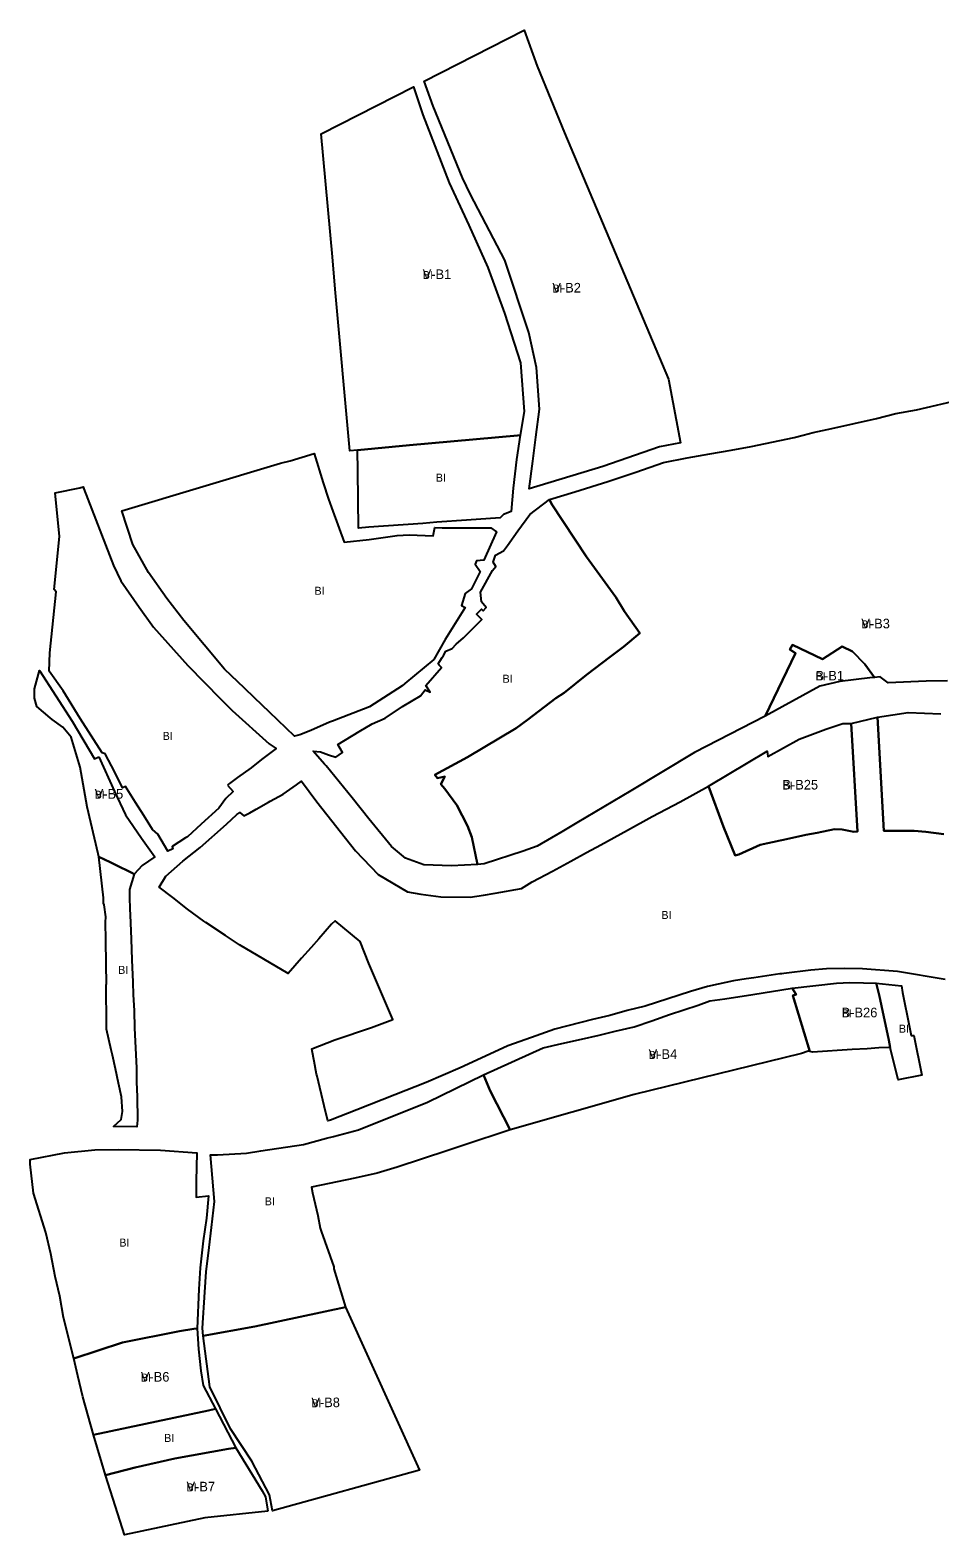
# Model space of a CAD drawing. Extents: x -532081 to -530154, y -1179372 to -1177675.
# Drawn here: x -532081 to -531512, y -1178734 to -1177794 of the extents above; entities that cross this region are included whole.
import ezdxf

# ---------------------------------------------------------------- set-up
doc = ezdxf.new("R2010")
doc.units = 0
for name, color, linetype in [('90040013', 7, 'Continuous'), ('90040023', 7, 'Continuous'), ('ID_navrh', 7, 'Continuous')]:
    doc.layers.add(name, color=color, linetype=linetype)

msp = doc.modelspace()

# ---------------------------------------------------------------- linework, layer by layer
at = {"layer": '90040013'}
for points in [[(-531869.34, -1178104.69), (-531875.73, -1178105.32), (-531876.21, -1178069.69), (-531876.39, -1178056.56), (-531843.89, -1178053.44), (-531776.3, -1178047.25), (-531774.57, -1178047.09), (-531777.03, -1178062.36), (-531779.14, -1178080.32), (-531780.38, -1178094.84), (-531785, -1178096.75), (-531787.18, -1178098.75), (-531808.2, -1178100.27), (-531826.84, -1178101.48), (-531835.46, -1178102.28)], [(-531891.83, -1178094.67), (-531884.75, -1178114.05), (-531869.14, -1178112.33), (-531851.53, -1178109.85), (-531844.08, -1178109.36), (-531828.99, -1178110.03), (-531827.93, -1178104.93), (-531823.39, -1178104.95), (-531808.92, -1178104.95), (-531792.99, -1178104.95), (-531789.36, -1178107.5), (-531797.35, -1178125.35), (-531801.89, -1178125.72), (-531802.8, -1178127.72), (-531799.71, -1178132.28), (-531805.16, -1178143.21), (-531808.97, -1178146.12), (-531811.33, -1178153.49), (-531809.01, -1178154.87), (-531821.49, -1178174.83), (-531828.69, -1178187.35), (-531846.79, -1178202.32), (-531848.46, -1178203.7), (-531868.8, -1178216.93), (-531892, -1178225.95), (-531893.87, -1178226.53), (-531905.46, -1178231.71), (-531912.28, -1178234.48), (-531915.73, -1178235.21), (-531931.35, -1178220.27), (-531940.66, -1178211.34), (-531947.04, -1178205.21), (-531959.4, -1178193.44), (-531984.96, -1178162.97), (-531995.52, -1178149.27), (-532006.96, -1178132.89), (-532016.83, -1178115.38), (-532023.59, -1178094.39), (-531924.56, -1178064.67), (-531918.32, -1178063.14), (-531903.47, -1178058.5), (-531897.72, -1178076.91), (-531894.55, -1178087.08)], [(-531957.63, -1178265.86), (-531953.96, -1178269.83), (-531958.6, -1178274.13), (-531962.95, -1178280.23), (-531974.02, -1178290.23), (-531982.67, -1178298.09), (-531983.81, -1178298.74), (-531992.09, -1178304.24), (-531991.69, -1178305.71), (-531994.9, -1178307.05), (-532001.07, -1178296.47), (-532004.5, -1178293.46), (-532009.87, -1178284.73), (-532015.13, -1178276.66), (-532021.24, -1178266.65), (-532023.21, -1178267.49), (-532028.1, -1178257.78), (-532034.09, -1178246.23), (-532035.93, -1178245.59), (-532049.67, -1178224.22), (-532060.29, -1178206.94), (-532069.01, -1178194.64), (-532068.69, -1178183.15), (-532064.73, -1178145.04), (-532066.02, -1178143.52), (-532062.58, -1178110.48), (-532065.33, -1178083.08), (-532049.98, -1178080.01), (-532047.73, -1178079.39), (-532047.4, -1178080.59), (-532028.78, -1178128.58), (-532024.19, -1178138.06), (-532012.87, -1178154.65), (-532003.91, -1178167.19), (-531982.44, -1178191.09), (-531961.68, -1178212.15), (-531954.6, -1178219.23), (-531931.63, -1178239.92), (-531927.24, -1178243.01), (-531936.39, -1178249.88), (-531942.73, -1178255.03), (-531951.41, -1178260.97), (-531956.26, -1178264.79), (-531956.93, -1178265.31)], [(-531714.94, -1178148.44), (-531709.43, -1178157.35), (-531699.82, -1178170.92), (-531710.05, -1178179.32), (-531718.44, -1178185.63), (-531733.12, -1178196.99), (-531747.18, -1178208.14), (-531752.37, -1178211.56), (-531770.1, -1178225.04), (-531777.2, -1178230.28), (-531807.62, -1178248.25), (-531827.96, -1178259.3), (-531826.25, -1178261.4), (-531821.69, -1178260.38), (-531824.23, -1178265.13), (-531821.77, -1178268.08), (-531814.18, -1178278.37), (-531807.61, -1178291.18), (-531804.87, -1178298.29), (-531801.44, -1178315.51), (-531817.69, -1178316.31), (-531834.9, -1178315.65), (-531846.42, -1178311.41), (-531855.06, -1178304.09), (-531869.28, -1178286.94), (-531879.65, -1178273.84), (-531895.97, -1178253.81), (-531896.87, -1178252.79), (-531904.04, -1178244.56), (-531899.49, -1178245.11), (-531894.41, -1178246.98), (-531889.85, -1178248.33), (-531885.68, -1178245.39), (-531888.72, -1178240.33), (-531875.23, -1178232.22), (-531867.25, -1178227.42), (-531859.06, -1178223.97), (-531848.13, -1178216.78), (-531837.01, -1178210), (-531834.12, -1178206.37), (-531830.91, -1178207.69), (-531833.63, -1178203.57), (-531823.9, -1178192.31), (-531825.21, -1178190.76), (-531825.87, -1178190.09), (-531824.89, -1178188.43), (-531823.49, -1178186.1), (-531822.67, -1178184.72), (-531821.08, -1178182.07), (-531817.23, -1178180.54), (-531814.7, -1178177.72), (-531810.08, -1178173.81), (-531800.1, -1178163.76), (-531798.6, -1178162.25), (-531801.88, -1178159), (-531798.82, -1178155.91), (-531797.83, -1178156.89), (-531795.83, -1178154.86), (-531798.8, -1178151.21), (-531799.42, -1178145.22), (-531792, -1178131.78), (-531789.8, -1178129.25), (-531791.49, -1178126.58), (-531790.08, -1178122.22), (-531785.18, -1178119.41), (-531782.65, -1178116.18), (-531776.13, -1178106.97), (-531768.71, -1178096.63), (-531756.44, -1178087.34), (-531755, -1178090.04), (-531733.11, -1178123.17)], [(-532013.79, -1178475.22), (-532014.33, -1178479.27), (-532028.88, -1178479.11), (-532023.99, -1178474.68), (-532023.15, -1178469.65), (-532023.87, -1178460.56), (-532025.66, -1178452.06), (-532027.68, -1178443.08), (-532029.51, -1178434.55), (-532030.37, -1178431.2), (-532033.16, -1178418.37), (-532033.27, -1178408.02), (-532033.47, -1178398.43), (-532033.47, -1178390.78), (-532033.25, -1178389.75), (-532033.47, -1178377.87), (-532033.47, -1178375.7), (-532033.7, -1178364.62), (-532033.7, -1178362.79), (-532033.82, -1178351.49), (-532033.57, -1178348.18), (-532034.76, -1178340.69), (-532035.1, -1178339.5), (-532035.1, -1178336.26), (-532037.98, -1178310.72), (-532030.86, -1178314.03), (-532027.54, -1178315.67), (-532017.48, -1178320.54), (-532015.89, -1178321.4), (-532018.86, -1178331.08), (-532018.86, -1178335.75), (-532018.61, -1178343.24), (-532018.49, -1178346.95), (-532017.74, -1178362.07), (-532017.37, -1178374.95), (-532016.81, -1178388.95), (-532016.63, -1178396.79), (-532015.88, -1178406.69), (-532015.7, -1178417.7), (-532015.14, -1178430.02), (-532014.44, -1178442.73), (-532014.44, -1178451.36), (-532014.05, -1178460.32)], [(-531531.32, -1178416.98), (-531530.29, -1178422.29), (-531528.71, -1178422.29), (-531523.7, -1178447.15), (-531538.47, -1178450.06), (-531543.48, -1178429.7), (-531544.27, -1178425.2), (-531548.91, -1178403.63), (-531550.26, -1178396.86), (-531552.21, -1178389.46), (-531536.27, -1178391.25), (-531535.62, -1178395.45)], [(-531940.58, -1178604.17), (-531972.85, -1178609.96), (-531973.25, -1178605.17), (-531971.85, -1178582.59), (-531970.86, -1178570), (-531969.07, -1178554.82), (-531967.59, -1178542.25), (-531965.63, -1178526.01), (-531968.12, -1178496.73), (-531963.85, -1178496.73), (-531945.7, -1178495.84), (-531936.8, -1178494.41), (-531910.1, -1178490.3), (-531895.69, -1178486.37), (-531891.41, -1178485.3), (-531875.76, -1178481.16), (-531832.63, -1178463.86), (-531797.68, -1178446.78), (-531793.48, -1178456.76), (-531780.88, -1178481.16), (-531809.85, -1178490.7), (-531819.98, -1178494.04), (-531851.65, -1178504.46), (-531864.04, -1178508.23), (-531878.07, -1178511.37), (-531905.12, -1178517.08), (-531904.53, -1178520.65), (-531901.14, -1178534.84), (-531899.7, -1178542.72), (-531898.95, -1178544.63), (-531891.18, -1178566.81), (-531891.18, -1178568), (-531883.81, -1178591.98)], [(-531977.26, -1178513.35), (-531977.26, -1178523.38), (-531969.43, -1178522.51), (-531970.74, -1178536.47), (-531972.7, -1178550.65), (-531974.65, -1178567.45), (-531975.52, -1178580.76), (-531976.57, -1178605.34), (-531978.58, -1178605.47), (-531987.54, -1178606.95), (-532023.25, -1178614.06), (-532053.53, -1178624.01), (-532060.1, -1178598.44), (-532062.47, -1178585.16), (-532065.23, -1178572.87), (-532068, -1178558.59), (-532071.1, -1178545.26), (-532078.93, -1178520.84), (-532080.97, -1178502.73), (-532080.97, -1178499.83), (-532059.55, -1178495.65), (-532040.48, -1178493.77), (-532026.01, -1178493.6), (-531999.45, -1178493.94), (-531976.8, -1178495.48)], [(-532015.3, -1178692.16), (-532033.93, -1178696.89), (-532041.26, -1178671.72), (-531969.39, -1178656.5), (-531965.15, -1178655.59), (-531952.37, -1178679.96), (-531956.87, -1178680.49), (-531990.45, -1178686.59)]]:
    msp.add_lwpolyline(points, close=True, dxfattribs=at)
msp.add_lwpolyline([(-531509.09, -1178387.21), (-531538.87, -1178382.3), (-531560.69, -1178380.6), (-531571.79, -1178380.41), (-531583.26, -1178380.6), (-531593.04, -1178381.35), (-531609.9, -1178383.53), (-531611.14, -1178383.8), (-531612.42, -1178383.8), (-531628.65, -1178386.19), (-531633.42, -1178386.91), (-531641.39, -1178388), (-531650.92, -1178390.16), (-531657.57, -1178391.6), (-531668.17, -1178394.67), (-531682.37, -1178399.25), (-531696.58, -1178403.83), (-531707.74, -1178406.63), (-531718.65, -1178409.69), (-531729.56, -1178412.23), (-531752.9, -1178418.34), (-531767.61, -1178423.43), (-531782.4, -1178428.62), (-531790.92, -1178432.6), (-531812.21, -1178442.57), (-531833.5, -1178451.7), (-531852.91, -1178459.31), (-531876.82, -1178468.63), (-531893.14, -1178475.26), (-531894.97, -1178475.68), (-531897.08, -1178466.23), (-531901.62, -1178447.73), (-531901.86, -1178446.33), (-531903.43, -1178438.26), (-531904.67, -1178431.8), (-531904.95, -1178430.53), (-531890.47, -1178424.89), (-531867.54, -1178417.27), (-531854.32, -1178412.33), (-531869.19, -1178377.34), (-531874.74, -1178363.59), (-531890.35, -1178350.54), (-531892.61, -1178352.62), (-531900.59, -1178361.85), (-531905.28, -1178367.24), (-531911.35, -1178373.86), (-531919.68, -1178383.6), (-531950.07, -1178365.6), (-531958.9, -1178359.83), (-531971.17, -1178351.55), (-531972.28, -1178350.74), (-531982.49, -1178343.28), (-531991.84, -1178336.1), (-532000.2, -1178329.58), (-531996.17, -1178322.74), (-531985.49, -1178313.42), (-531974.76, -1178304.88), (-531958.11, -1178290.13), (-531951.73, -1178284.22), (-531949.8, -1178282.87), (-531947.36, -1178285.05), (-531943.73, -1178283.03), (-531939.62, -1178280.75), (-531932.03, -1178276.53), (-531930.84, -1178275.92), (-531922.86, -1178271.53), (-531914.53, -1178265.55), (-531911.34, -1178263.25), (-531901.73, -1178276.35), (-531877.53, -1178306.79), (-531863.37, -1178321.76), (-531845.04, -1178332.53), (-531836.71, -1178334.01), (-531824.31, -1178335.68), (-531805.98, -1178335.87), (-531797.65, -1178334.57), (-531790.25, -1178333.27), (-531773.77, -1178330.49), (-531767.11, -1178326.21), (-531754.53, -1178319.68), (-531743.05, -1178313.37), (-531733.24, -1178307.98), (-531724.17, -1178303.16), (-531707.69, -1178293.87), (-531692.14, -1178285.33), (-531674.73, -1178276.23), (-531656.96, -1178266.46), (-531647.51, -1178291.8), (-531640.37, -1178309.78), (-531638.81, -1178309.43), (-531637.97, -1178309.1), (-531624.62, -1178303.19), (-531612.27, -1178300.39), (-531611.07, -1178300.19), (-531602.5, -1178298.39), (-531596.13, -1178296.79), (-531588.96, -1178295.6), (-531578.2, -1178293.4), (-531573.42, -1178293.6), (-531566.05, -1178295), (-531563.86, -1178294.8), (-531567.74, -1178227.33), (-531551.32, -1178223.26), (-531547.32, -1178294.4), (-531533.38, -1178294.4), (-531528.4, -1178294.43), (-531521.2, -1178294.91), (-531509.87, -1178296.36)], dxfattribs=at)
at = {"layer": '90040023'}
for points in [[(-531681.94, -1178012.18), (-531674.51, -1178052.02), (-531687.56, -1178054.45), (-531722.99, -1178066.65), (-531768.97, -1178080.72), (-531766.81, -1178063.34), (-531764.84, -1178048.37), (-531762.55, -1178030.99), (-531764.36, -1178004.77), (-531769.2, -1177983.08), (-531784.19, -1177937.7), (-531805.73, -1177896.68), (-531810.63, -1177886.29), (-531829.04, -1177841.54), (-531834.6, -1177825.98), (-531772.14, -1177794.03), (-531764.08, -1177816.59), (-531746.96, -1177858.19)], [(-531806.82, -1177915.91), (-531794.88, -1177942.31), (-531784.44, -1177970.99), (-531774.39, -1178002.04), (-531772.2, -1178032.42), (-531774.57, -1178047.09), (-531776.3, -1178047.25), (-531843.89, -1178053.44), (-531876.39, -1178056.56), (-531881.16, -1178057.02), (-531890.23, -1177955.99), (-531892.05, -1177935.77), (-531898.95, -1177858.9), (-531841.29, -1177829.4), (-531835.41, -1177846.99), (-531819.04, -1177889.54)], [(-531587.35, -1178204.08), (-531621.48, -1178222.74), (-531602.61, -1178183.33), (-531606.12, -1178181.13), (-531604.37, -1178178.05), (-531585.71, -1178187.08), (-531573.42, -1178179.15), (-531567.06, -1178182.23), (-531559.16, -1178190.16), (-531553.23, -1178198.52), (-531556.2, -1178198.76), (-531574.89, -1178201.07)], [(-532038.1, -1178248.16), (-532028.29, -1178269.7), (-532021.24, -1178284.39), (-532011.34, -1178298.87), (-532002.92, -1178310.67), (-532010.94, -1178316.04), (-532015.89, -1178321.4), (-532017.48, -1178320.54), (-532027.54, -1178315.67), (-532030.86, -1178314.03), (-532037.98, -1178310.72), (-532038.32, -1178308.67), (-532045.3, -1178279.39), (-532049.66, -1178254.64), (-532055.2, -1178235.85), (-532060.6, -1178229.5), (-532067.2, -1178224.74), (-532068.35, -1178223.7), (-532076.69, -1178216.63), (-532078.26, -1178211.4), (-532078.26, -1178205.64), (-532075.13, -1178194.13), (-532054.62, -1178225.87), (-532040.66, -1178249.44)], [(-531624.62, -1178303.19), (-531637.97, -1178309.1), (-531638.81, -1178309.43), (-531640.37, -1178309.78), (-531647.51, -1178291.8), (-531656.96, -1178266.46), (-531620.26, -1178244.62), (-531619.86, -1178247.87), (-531600.39, -1178237.09), (-531583.56, -1178230.79), (-531573.01, -1178227.33), (-531567.74, -1178227.33), (-531563.86, -1178294.8), (-531566.05, -1178295), (-531573.42, -1178293.6), (-531578.2, -1178293.4), (-531588.96, -1178295.6), (-531596.13, -1178296.79), (-531602.5, -1178298.39), (-531611.07, -1178300.19), (-531612.27, -1178300.39)], [(-531593.59, -1178432.2), (-531604.33, -1178397.2), (-531602.27, -1178396.58), (-531604.74, -1178392.64), (-531576.94, -1178389.6), (-531568.7, -1178389.18), (-531560.18, -1178389.32), (-531552.21, -1178389.46), (-531550.26, -1178396.86), (-531548.91, -1178403.63), (-531544.27, -1178425.2), (-531543.48, -1178429.7), (-531550.59, -1178429.96), (-531557.71, -1178430.49), (-531567.2, -1178431.02), (-531591.89, -1178432.61), (-531593.56, -1178432.29)], [(-531703.35, -1178459.18), (-531780.88, -1178481.16), (-531793.48, -1178456.76), (-531797.68, -1178446.78), (-531760.31, -1178429.91), (-531748.64, -1178427.33), (-531736.39, -1178424.58), (-531725.27, -1178421.99), (-531715.28, -1178419.57), (-531703.35, -1178416.82), (-531692.39, -1178413.1), (-531681.27, -1178409.22), (-531663.5, -1178403.23), (-531656.03, -1178400.51), (-531646.8, -1178399.28), (-531629.15, -1178396.56), (-531604.74, -1178392.64), (-531602.27, -1178396.58), (-531604.33, -1178397.2), (-531593.59, -1178432.2), (-531593.56, -1178432.29), (-531594.63, -1178432.09), (-531598.81, -1178433.42)], [(-531883.81, -1178591.98), (-531837.49, -1178693.81), (-531929.55, -1178719.18), (-531931.29, -1178709.21), (-531942.39, -1178688.18), (-531955.64, -1178668.08), (-531968.59, -1178641.79), (-531972.85, -1178609.96), (-531940.58, -1178604.17)], [(-531965.15, -1178655.59), (-531969.39, -1178656.5), (-532041.26, -1178671.72), (-532047.94, -1178648.1), (-532051.23, -1178634.9), (-532053.53, -1178624.01), (-532023.25, -1178614.06), (-531987.54, -1178606.95), (-531978.58, -1178605.47), (-531976.57, -1178605.34), (-531975.61, -1178618.18), (-531974.24, -1178631.71), (-531972.73, -1178640.99)], [(-531932.28, -1178719.47), (-531971.67, -1178723.72), (-532021.94, -1178734.32), (-532026.16, -1178721.18), (-532033.93, -1178696.89), (-532015.3, -1178692.16), (-531990.45, -1178686.59), (-531956.87, -1178680.49), (-531952.37, -1178679.96), (-531935.98, -1178706.74), (-531933.87, -1178710.46)]]:
    msp.add_lwpolyline(points, close=True, dxfattribs=at)
for points in [[(-531507.5, -1178200.57), (-531520.9, -1178200.8), (-531544.75, -1178201.94), (-531549.74, -1178198.06), (-531553.23, -1178198.52), (-531559.16, -1178190.16), (-531567.06, -1178182.23), (-531573.42, -1178179.15), (-531585.71, -1178187.08), (-531604.37, -1178178.05), (-531606.12, -1178181.13), (-531602.61, -1178183.33), (-531621.48, -1178222.74), (-531665.8, -1178245.38), (-531705.57, -1178269.37), (-531739.2, -1178289.34), (-531748.58, -1178295.08), (-531764.14, -1178304.03), (-531772.84, -1178307.01), (-531797.09, -1178315.05), (-531801.44, -1178315.51), (-531804.87, -1178298.29), (-531807.61, -1178291.18), (-531814.18, -1178278.37), (-531821.77, -1178268.08), (-531824.23, -1178265.13), (-531821.69, -1178260.38), (-531826.25, -1178261.4), (-531827.96, -1178259.3), (-531807.62, -1178248.25), (-531777.2, -1178230.28), (-531770.1, -1178225.04), (-531752.37, -1178211.56), (-531747.18, -1178208.14), (-531733.12, -1178196.99), (-531718.44, -1178185.63), (-531710.05, -1178179.32), (-531699.82, -1178170.92), (-531709.43, -1178157.35), (-531714.94, -1178148.44), (-531733.11, -1178123.17), (-531755, -1178090.04), (-531756.44, -1178087.34), (-531740.54, -1178082.58), (-531719.9, -1178076.16), (-531702.35, -1178070.36), (-531685, -1178064.15), (-531670.34, -1178061.25), (-531656.1, -1178058.76), (-531642.71, -1178056.59), (-531630.27, -1178054.13), (-531603.4, -1178048.57), (-531597.86, -1178047.18), (-531591.49, -1178045.52), (-531579.86, -1178043.02), (-531551.89, -1178036.63), (-531539.98, -1178033.57), (-531526.97, -1178031.35), (-531498.44, -1178024.68)], [(-531509.87, -1178296.36), (-531521.2, -1178294.91), (-531528.4, -1178294.43), (-531533.38, -1178294.4), (-531547.32, -1178294.4), (-531551.32, -1178223.26), (-531532.26, -1178220.41), (-531511.78, -1178221.23)]]:
    msp.add_lwpolyline(points, dxfattribs=at)

# ---------------------------------------------------------------- texts
at = {"layer": '90040013'}
for rotation, p in [(0, (-531827.39, -1178076.2)), (0, (-531903.21, -1178146.86)), (360, (-531785.67, -1178201.83)), (360, (-531998.12, -1178237.57)), (360, (-531686.39, -1178349.47)), (0, (-532025.88, -1178383.76)), (360, (-531537.96, -1178420.51)), (360, (-531934.3, -1178528.37)), (360, (-532025.2, -1178554.16)), (0, (-531997.13, -1178676.24))]:
    msp.add_text('BI', height=5, rotation=rotation, dxfattribs=at).set_placement(p)
at = {"layer": '90040023'}
for rotation, p in [(0, (-531835.58, -1177949.58)), (0, (-531754.56, -1177958.01)), (0, (-531561.44, -1178167.86)), (360, (-531590.11, -1178200.4)), (0, (-531610.77, -1178268.55)), (0, (-532040.59, -1178274.28)), (0, (-531573.74, -1178410.9)), (0, (-531694.37, -1178436.9)), (0, (-532011.72, -1178638.53)), (0, (-531983.2, -1178707.14))]:
    msp.add_text('BI', height=5, rotation=rotation, dxfattribs=at).set_placement(p)
msp.add_text('BI', height=5, dxfattribs=at).set_placement((-531905.17, -1178654.51))
at = {"layer": 'ID_navrh'}
for s, rotation, p in [('V-B1', 0, (-531835.58, -1177949.58)), ('V-B2', 0, (-531754.56, -1177958.01)), ('V-B3', 0, (-531561.44, -1178167.86)), ('B-B1', 360, (-531590.11, -1178200.4)), ('B-B25', 0, (-531610.77, -1178268.55)), ('V-B5', 0, (-532040.59, -1178274.28)), ('B-B26', 0, (-531573.74, -1178410.9)), ('V-B4', 0, (-531694.37, -1178436.9)), ('V-B6', 0, (-532011.72, -1178638.53)), ('V-B8', 360, (-531905.17, -1178654.51)), ('V-B7', 0, (-531983.2, -1178707.14))]:
    msp.add_text(s, height=6, rotation=rotation, dxfattribs=at).set_placement(p)

doc.saveas('drawing.dxf')
